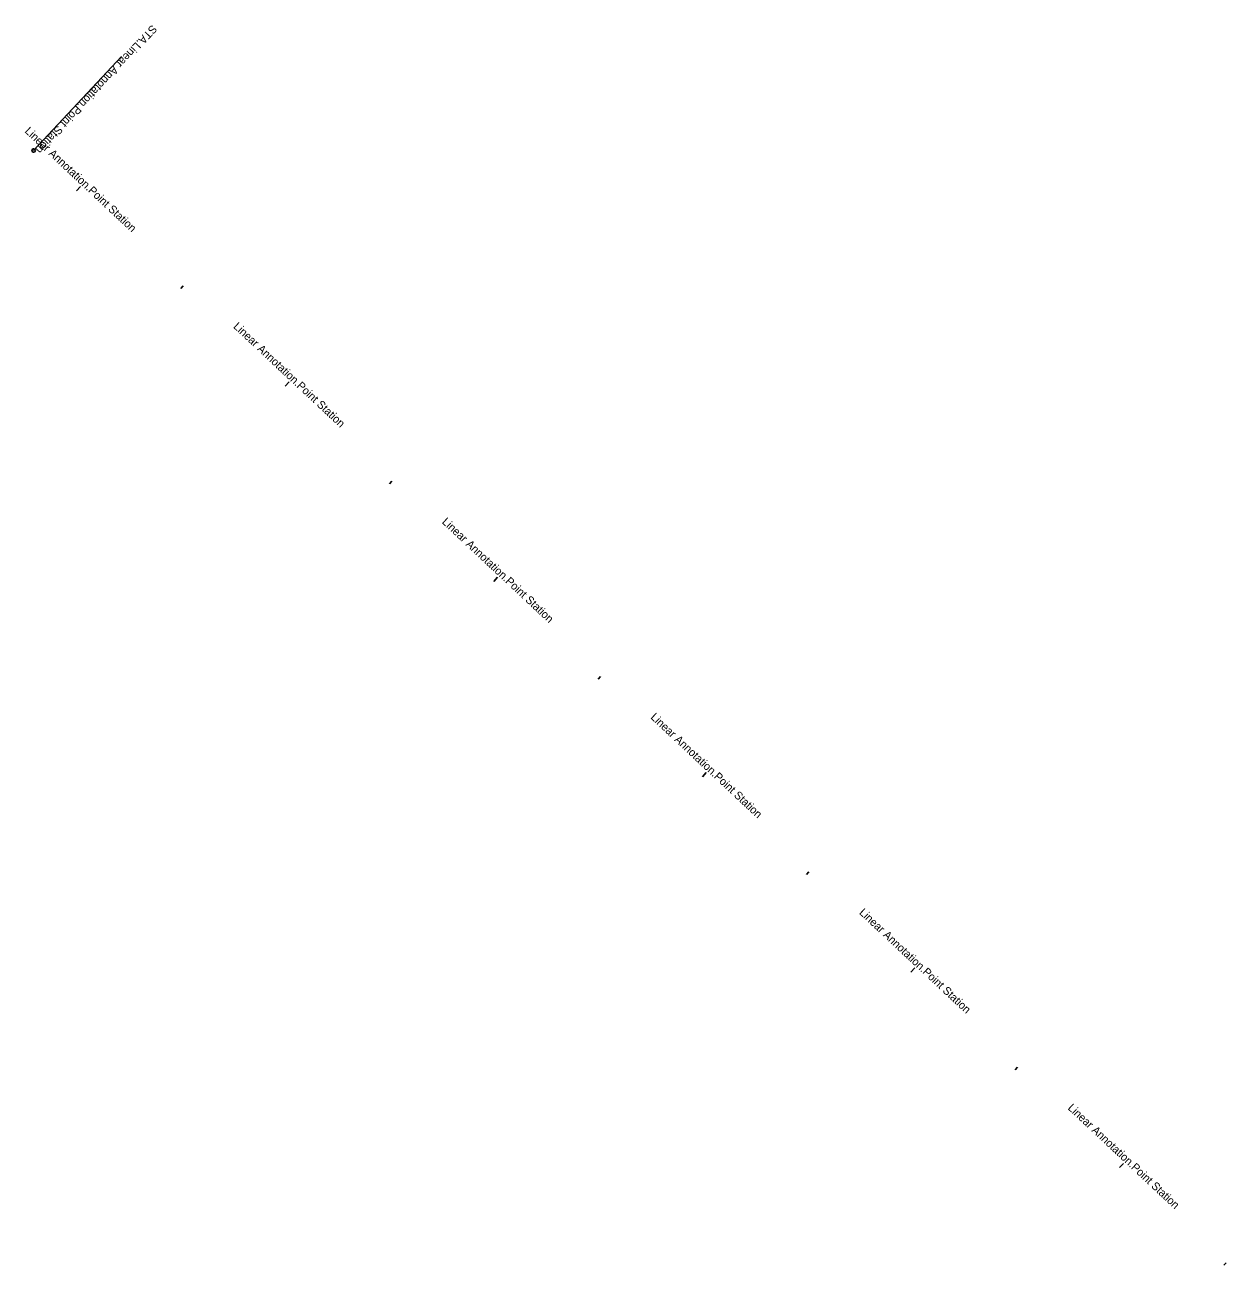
# Model space of a CAD drawing. Extents: x 1470334 to 1481646, y 379063 to 388330.
# Drawn here: x 1479563.6 to 1479984, y 379599.6 to 380033.5 of the extents above; entities that cross this region are included whole.
import ezdxf

# ---------------------------------------------------------------- set-up
doc = ezdxf.new("R2010")
doc.units = 0
doc.layers.add('Default', color=7, linetype='Continuous')

msp = doc.modelspace()

# ---------------------------------------------------------------- linework, layer by layer
at = {"layer": 'Default'}
for p, q in [((1479566.69, 379989.53), (1479597.45, 380022.38)), ((1479566.69, 379989.53), (1479597.45, 380022.38)), ((1479581.7, 379975.48), (1479583.07, 379976.94)), ((1479581.7, 379975.48), (1479583.07, 379976.94)), ((1479618.2, 379941.31), (1479619.02, 379942.18)), ((1479618.2, 379941.31), (1479619.02, 379942.18)), ((1479654.7, 379907.13), (1479656.07, 379908.59)), ((1479654.7, 379907.13), (1479656.07, 379908.59)), ((1479691.2, 379872.96), (1479692.02, 379873.84)), ((1479691.2, 379872.96), (1479692.02, 379873.84)), ((1479727.7, 379838.79), (1479729.07, 379840.25)), ((1479727.7, 379838.79), (1479729.07, 379840.25)), ((1479764.2, 379804.62), (1479765.02, 379805.49)), ((1479764.2, 379804.62), (1479765.02, 379805.49)), ((1479800.7, 379770.44), (1479802.07, 379771.9)), ((1479800.7, 379770.44), (1479802.07, 379771.9)), ((1479837.2, 379736.27), (1479838.02, 379737.15)), ((1479837.2, 379736.27), (1479838.02, 379737.15)), ((1479873.7, 379702.1), (1479875.07, 379703.56)), ((1479873.7, 379702.1), (1479875.07, 379703.56)), ((1479910.2, 379667.92), (1479911.02, 379668.8)), ((1479910.2, 379667.92), (1479911.02, 379668.8)), ((1479946.7, 379633.75), (1479948.07, 379635.21)), ((1479946.7, 379633.75), (1479948.07, 379635.21)), ((1479983.2, 379599.58), (1479984.02, 379600.46)), ((1479983.2, 379599.58), (1479984.02, 379600.46))]:
    msp.add_line(p, q, dxfattribs=at)
msp.add_circle((1479566.69, 379989.53), 0.6, dxfattribs=at)
msp.add_circle((1479566.69, 379989.53), 0.6, dxfattribs=at)

# ---------------------------------------------------------------- texts
for s, rotation, p in [(' STA. ', 226.886, (1479608.83, 380034.48)), (' STA. ', 226.886, (1479608.83, 380034.48)), ('Linear Annotation.Point Station', 226.886, (1479602.45, 380027.68)), ('Linear Annotation.Point Station', 226.886, (1479602.45, 380027.68)), ('Linear Annotation.Point Station', 316.886, (1479563.37, 379996.06)), ('Linear Annotation.Point Station', 316.886, (1479563.37, 379996.06)), ('Linear Annotation.Point Station', 316.886, (1479636.37, 379927.72)), ('Linear Annotation.Point Station', 316.886, (1479636.37, 379927.72)), ('Linear Annotation.Point Station', 316.886, (1479709.37, 379859.37)), ('Linear Annotation.Point Station', 316.886, (1479709.37, 379859.37)), ('Linear Annotation.Point Station', 316.886, (1479782.37, 379791.03)), ('Linear Annotation.Point Station', 316.886, (1479782.37, 379791.03)), ('Linear Annotation.Point Station', 316.886, (1479855.37, 379722.68)), ('Linear Annotation.Point Station', 316.886, (1479855.37, 379722.68)), ('Linear Annotation.Point Station', 316.886, (1479928.37, 379654.34)), ('Linear Annotation.Point Station', 316.886, (1479928.37, 379654.34))]:
    msp.add_text(s, height=2.8, rotation=rotation, dxfattribs=at).set_placement(p)

doc.saveas('drawing.dxf')
